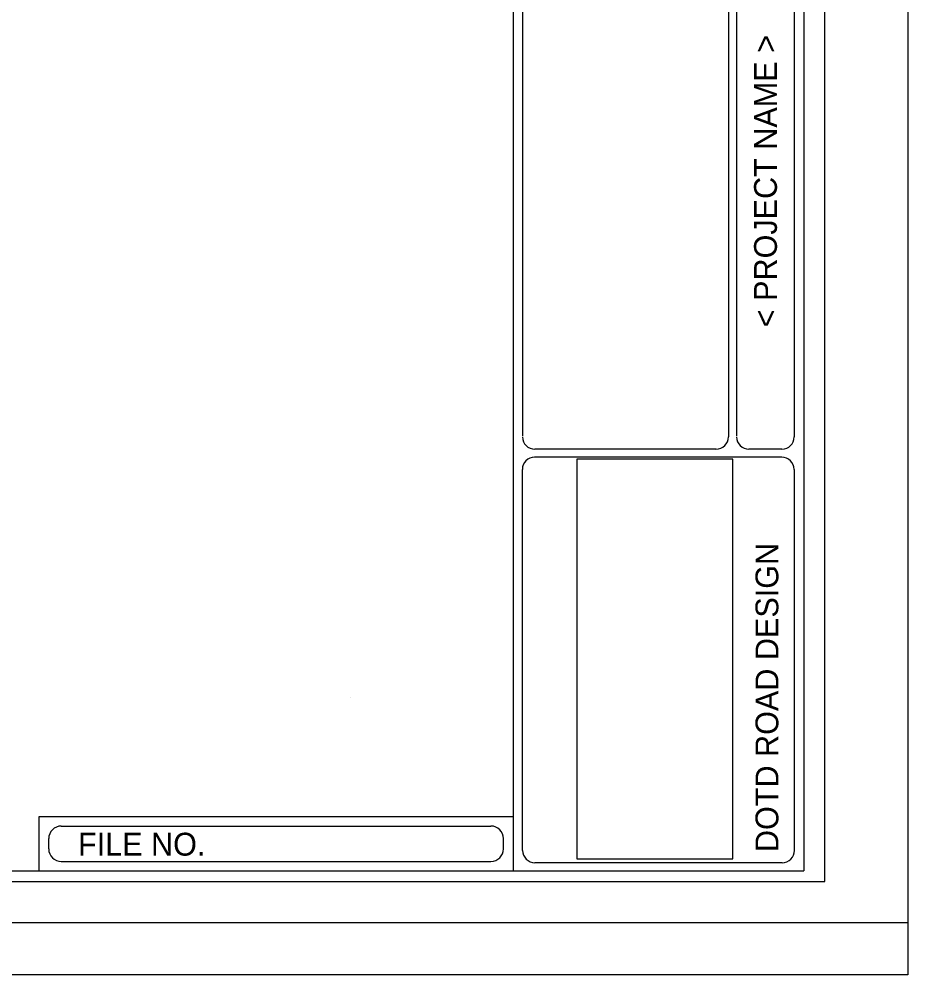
# Model space of a CAD drawing. Extents: x -31.4 to 41.1, y -13.7 to 22.3.
# Drawn here: x -1.443 to 2.833, y 0.04 to 4.638 of the extents above; entities that cross this region are included whole.
import ezdxf

# ---------------------------------------------------------------- set-up
doc = ezdxf.new("R2010")
doc.units = 0
for name, color, linetype in [('Construction Class', 7, 'Continuous'), ('Plot Border', 7, 'Continuous'), ('Plot Border 2', 7, 'Continuous'), ('Seal', 7, 'Continuous'), ('Sheet Border', 7, 'Continuous')]:
    doc.layers.add(name, color=color, linetype=linetype)

msp = doc.modelspace()

# ---------------------------------------------------------------- linework, layer by layer
at = {"layer": 'Construction Class'}
msp.add_line((0.15, 1.375), (0.15, 1.375), dxfattribs=at)
at = {"layer": 'Plot Border'}
for points in [[(-31.1667, 22.0397), (2.8333, 22.0397), (2.8333, 0.0396), (-31.1667, 0.0396)], [(2.4333, 21.5897), (-30.5667, 21.5897), (-30.5667, 0.4896), (2.4333, 0.4896)]]:
    msp.add_lwpolyline(points, close=True, dxfattribs=at)
at = {"layer": 'Plot Border 2'}
msp.add_lwpolyline([(-31.1667, 21.7897), (2.8333, 21.7897), (2.8333, 0.2896), (-31.1667, 0.2896)], close=True, dxfattribs=at)
at = {"layer": 'Seal'}
msp.add_lwpolyline([(1.9905, 0.5973), (1.9905, 2.5205), (1.2412, 2.5205), (1.2412, 0.5973)], close=True, dxfattribs=at)
at = {"layer": 'Sheet Border'}
for p, q in [((0.9333, 21.5397), (0.9333, 0.5396)), ((2.3333, 21.5397), (2.3333, 0.5396)), ((0.9791, 6.9883), (0.9791, 2.6322)), ((0.9791, 6.9882), (0.9791, 2.6322)), ((1.9696, 6.9838), (1.9696, 2.6278)), ((2.0093, 6.9882), (2.0093, 2.6322)), ((2.2866, 6.9838), (2.2866, 2.6278)), ((2.2262, 2.5302), (1.0375, 2.5302)), ((1.9102, 2.5684), (1.0385, 2.5684)), ((2.2272, 2.5684), (2.0687, 2.5684)), ((0.9781, 2.4708), (0.9781, 0.6387)), ((2.2856, 2.4708), (2.2856, 0.6387)), ((-1.3467, 0.5396), (-1.3467, 0.8016)), ((-1.2407, 0.7556), (0.8273, 0.7556)), ((-1.3007, 0.6456), (-1.3007, 0.6956)), ((0.8873, 0.6456), (0.8873, 0.6956)), ((-1.2407, 0.5856), (0.8273, 0.5856)), ((2.2282, 0.5793), (1.039, 0.5793)), ((-29.1667, 0.5396), (2.3333, 0.5396))]:
    msp.add_line(p, q, dxfattribs=at)
msp.add_lwpolyline([(-1.3467, 0.8016), (0.9333, 0.8016)], dxfattribs=at)
for centre, radius, start, end in [((1.0383, 2.6278), 0.0594, 180, 270), ((1.91, 2.6278), 0.0594, 270, 0), ((2.0685, 2.6278), 0.0594, 180, 270), ((2.227, 2.6278), 0.0594, 270, 0), ((1.0377, 2.471), 0.0594, 90, 180), ((2.2263, 2.471), 0.0594, 0, 90), ((-1.2407, 0.6956), 0.06, 90, 180), ((0.8273, 0.6956), 0.06, 0, 90), ((-1.2407, 0.6456), 0.06, 180, 270), ((0.8273, 0.6456), 0.06, 270, 0), ((1.039, 0.6387), 0.0594, 180, 270), ((2.2282, 0.6387), 0.0594, 270, 360)]:
    msp.add_arc(centre, radius, start, end, dxfattribs=at)

# ---------------------------------------------------------------- texts
for s, p in [('               < PROJECT NAME >               ', (2.2032, 2.5422)), (' DOTD ROAD DESIGN', (2.2101, 0.5896))]:
    msp.add_text(s, height=0.11, rotation=90, dxfattribs=at).set_placement(p)
msp.add_text('FILE NO.', height=0.11, dxfattribs=at).set_placement((-1.1598, 0.6134))

doc.saveas('drawing.dxf')
